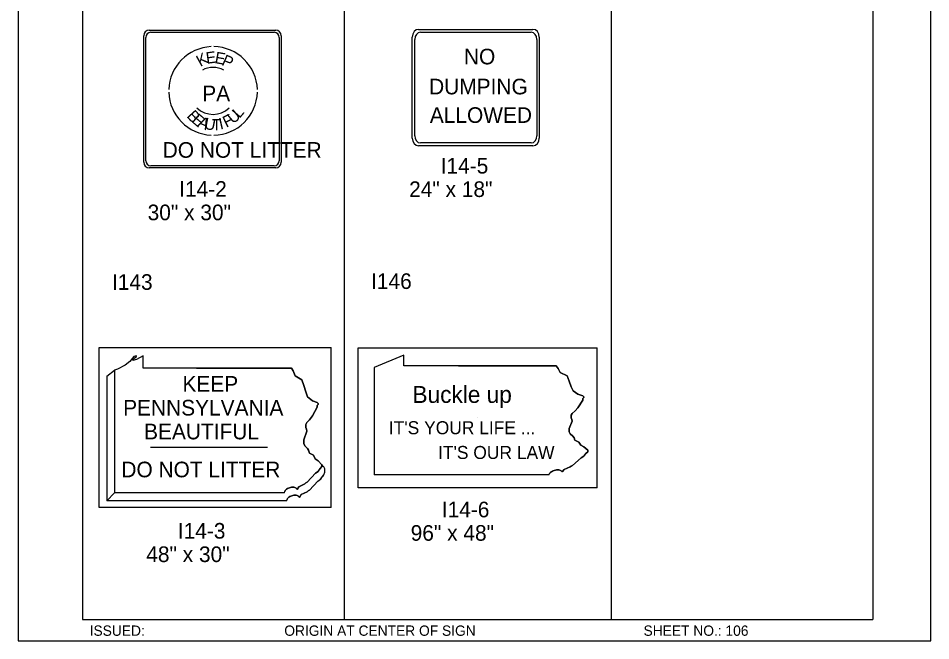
# Model space of a CAD drawing. Extents: x -5299 to 22597, y -19549 to -1808.
# Drawn here: x 14332 to 15033, y -5462 to -4984 of the extents above; entities that cross this region are included whole.
import ezdxf

# ---------------------------------------------------------------- set-up
doc = ezdxf.new("R2010")
doc.units = 0
for name, color, linetype in [('Level 1', 7, 'Continuous'), ('Level 2', 7, 'Continuous'), ('Level 3', 7, 'Continuous'), ('Level 61', 7, 'Continuous')]:
    doc.layers.add(name, color=color, linetype=linetype)

msp = doc.modelspace()

# ---------------------------------------------------------------- linework, layer by layer
at = {"layer": 'Level 1'}
for p, q in [((14381.92, -4645.77), (14381.92, -5445.77)), ((14582.85, -4645.77), (14582.85, -5445.77)), ((14788.01, -4645.77), (14788.01, -5445.77)), ((14988.94, -4645.77), (14988.94, -5445.77)), ((14428.81, -5094.6), (14428.81, -4997.4)), ((14433.04, -4993.17), (14530.24, -4993.17)), ((14434.29, -4994.74), (14528.99, -4994.74)), ((14534.47, -4997.4), (14534.47, -5094.6)), ((14635.19, -5075.98), (14635.19, -4998.46)), ((14640.07, -4992.5), (14727.85, -4992.5)), ((14641.55, -4994.74), (14726.41, -4994.74)), ((14732.73, -4998.46), (14732.73, -5075.98)), ((14430.38, -5093.35), (14430.38, -4998.65)), ((14532.9, -4998.65), (14532.9, -5093.35)), ((14637.04, -5074.2), (14637.04, -5000.25)), ((14730.92, -5000.25), (14730.92, -5074.2)), ((14481.64, -5046), (14481.64, -5046)), ((14727.85, -5081.95), (14640.07, -5081.95)), ((14726.41, -5079.71), (14641.55, -5079.71)), ((14530.24, -5098.83), (14433.04, -5098.83)), ((14528.99, -5097.26), (14434.29, -5097.26)), ((14394.57, -5359.75), (14394.57, -5236.72)), ((14394.57, -5236.72), (14572.74, -5236.72)), ((14572.74, -5359.75), (14572.74, -5236.72)), ((14593.68, -5344.56), (14593.68, -5237)), ((14593.68, -5237), (14777.18, -5237)), ((14628.67, -5242.65), (14605.98, -5252.28)), ((14628.67, -5251.03), (14628.67, -5242.65)), ((14777.18, -5344.56), (14777.18, -5237)), ((14400.53, -5258.98), (14406.51, -5254.2)), ((14685.43, -5290.78), (14685.43, -5290.78)), ((14483.65, -5298.24), (14483.65, -5298.24)), ((14434.08, -5313.47), (14523.85, -5313.47)), ((14758.34, -5327.45), (14764.85, -5321.49)), ((14554.44, -5340.19), (14560.76, -5333.36)), ((14740.45, -5334.75), (14605.95, -5334.75)), ((14740.45, -5334.75), (14605.95, -5334.75)), ((14740.45, -5334.75), (14740.57, -5333.71)), ((14740.45, -5334.75), (14740.57, -5333.71)), ((14740.45, -5334.75), (14740.57, -5333.71)), ((14556.21, -5346.28), (14562.52, -5339.46)), ((14406.48, -5348.58), (14400.51, -5354.55)), ((14537.07, -5348.53), (14406.48, -5348.53)), ((14537.07, -5348.53), (14406.48, -5348.53)), ((14537.07, -5348.53), (14537.19, -5347.34)), ((14537.07, -5348.53), (14537.19, -5347.34)), ((14537.07, -5348.53), (14537.19, -5347.34)), ((14777.18, -5344.56), (14593.68, -5344.56)), ((14538.84, -5354.63), (14400.51, -5354.63)), ((14538.84, -5354.63), (14408.25, -5354.63)), ((14538.84, -5354.63), (14408.25, -5354.63)), ((14538.84, -5354.63), (14538.95, -5353.44)), ((14538.84, -5354.63), (14538.95, -5353.44)), ((14538.84, -5354.63), (14538.95, -5353.44)), ((14572.74, -5359.75), (14394.57, -5359.75)), ((14381.92, -5445.77), (14988.94, -5445.77))]:
    msp.add_line(p, q, dxfattribs=at)
for points in [[(14469.38, -5252.76), (14428.54, -5252.76), (14428.48, -5243.18), (14423.39, -5246.09), (14420.51, -5246.82), (14421.2, -5245.38), (14423.39, -5243.86), (14423.41, -5243.18), (14421.18, -5243.86), (14418.26, -5247.53), (14414.66, -5250.49), (14408.71, -5253.47), (14406.51, -5254.2)], [(14406.51, -5254.2), (14406.48, -5348.53)], [(14560.76, -5333.36), (14562.82, -5331.95), (14564.33, -5329.73), (14565.75, -5328.27), (14565.77, -5326.87), (14562.77, -5323.89), (14560.59, -5322.44), (14559.16, -5319.56), (14556.2, -5318.03), (14555.48, -5315.79), (14554.73, -5314.35), (14552.59, -5312.24), (14551.75, -5310.69), (14551.81, -5307.79), (14554.03, -5301.13), (14553.97, -5299.68), (14553.26, -5298.23), (14553.28, -5296.05), (14553.26, -5296.08), (14554.03, -5294.53), (14556.27, -5292.29), (14558.42, -5289.39), (14562.09, -5282.78), (14562.07, -5282.75), (14562.09, -5281.33), (14562.82, -5280.58), (14562.81, -5279.9), (14562.06, -5279.12), (14558.42, -5277.67), (14554.75, -5274.72), (14553.28, -5271.01), (14551.88, -5266.08), (14550.33, -5261.55), (14545.2, -5258.57), (14543.68, -5254.86), (14542.27, -5252.75), (14469.38, -5252.76)], [(14560.76, -5333.36), (14562.82, -5331.95), (14564.33, -5329.73), (14565.75, -5328.27), (14565.77, -5326.87), (14562.77, -5323.89), (14560.59, -5322.44), (14559.16, -5319.56), (14556.2, -5318.03), (14555.48, -5315.79), (14554.73, -5314.35), (14552.59, -5312.24), (14551.75, -5310.69), (14551.81, -5307.79), (14554.03, -5301.13), (14553.97, -5299.68), (14553.26, -5298.23), (14553.28, -5296.05), (14553.26, -5296.08), (14554.03, -5294.53), (14556.27, -5292.29), (14558.42, -5289.39), (14562.09, -5282.78), (14562.07, -5282.75), (14562.09, -5281.33), (14562.82, -5280.58), (14562.81, -5279.9), (14562.06, -5279.12), (14558.42, -5277.67), (14554.75, -5274.72), (14553.28, -5271.01), (14551.88, -5266.08), (14550.33, -5261.55), (14545.2, -5258.57), (14543.68, -5254.86), (14542.27, -5252.75), (14469.38, -5252.76)], [(14469.38, -5252.76), (14542.27, -5252.75), (14543.68, -5254.86), (14545.2, -5258.57), (14550.33, -5261.55), (14551.88, -5266.08), (14553.28, -5271.01), (14554.75, -5274.72), (14558.42, -5277.67), (14562.06, -5279.12), (14562.81, -5279.9), (14562.82, -5280.58), (14562.09, -5281.33), (14562.07, -5282.75), (14562.09, -5282.78), (14558.42, -5289.39), (14556.27, -5292.29), (14554.03, -5294.53), (14553.26, -5296.08), (14553.28, -5296.05), (14553.26, -5298.23), (14553.97, -5299.68), (14554.03, -5301.13), (14551.81, -5307.79), (14551.75, -5310.69), (14552.59, -5312.24), (14554.73, -5314.35), (14555.48, -5315.79), (14556.2, -5318.03), (14559.16, -5319.56), (14560.59, -5322.44), (14562.77, -5323.89), (14565.77, -5326.87), (14565.75, -5328.27), (14564.33, -5329.73), (14562.92, -5331.81)], [(14605.98, -5252.28), (14605.95, -5334.75)], [(14764.85, -5321.49), (14766.97, -5320.26), (14768.53, -5318.31), (14769.99, -5317.04), (14770, -5315.81), (14766.92, -5313.21), (14764.67, -5311.94), (14763.2, -5309.42), (14760.15, -5308.08), (14759.41, -5306.12), (14758.64, -5304.87), (14756.43, -5303.02), (14755.57, -5301.66), (14755.63, -5299.13), (14757.91, -5293.31), (14757.85, -5292.04), (14757.13, -5290.77), (14757.14, -5288.86), (14757.13, -5288.89), (14757.91, -5287.54), (14760.22, -5285.58), (14762.44, -5283.05), (14766.22, -5277.27), (14766.2, -5277.24), (14766.22, -5276), (14766.97, -5275.34), (14766.95, -5274.74), (14766.18, -5274.06), (14762.44, -5272.8), (14758.65, -5270.22), (14757.14, -5266.98), (14755.7, -5262.67), (14754.11, -5258.7), (14748.82, -5256.1), (14747.25, -5252.86), (14745.81, -5251.02), (14628.67, -5251.03)], [(14764.85, -5321.49), (14766.97, -5320.26), (14768.53, -5318.31), (14769.99, -5317.04), (14770, -5315.81), (14766.92, -5313.21), (14764.67, -5311.94), (14763.2, -5309.42), (14760.15, -5308.08), (14759.41, -5306.12), (14758.64, -5304.87), (14756.43, -5303.02), (14755.57, -5301.66), (14755.63, -5299.13), (14757.91, -5293.31), (14757.85, -5292.04), (14757.13, -5290.77), (14757.14, -5288.86), (14757.13, -5288.89), (14757.91, -5287.54), (14760.22, -5285.58), (14762.44, -5283.05), (14766.22, -5277.27), (14766.2, -5277.24), (14766.22, -5276), (14766.97, -5275.34), (14766.95, -5274.74), (14766.18, -5274.06), (14762.44, -5272.8), (14758.65, -5270.22), (14757.14, -5266.98), (14755.7, -5262.67), (14754.11, -5258.7), (14748.82, -5256.1), (14747.25, -5252.86), (14745.81, -5251.02), (14670.74, -5251.02)], [(14670.74, -5251.02), (14745.81, -5251.02), (14747.25, -5252.86), (14748.82, -5256.1), (14754.11, -5258.7), (14755.7, -5262.67), (14757.14, -5266.98), (14758.65, -5270.22), (14762.44, -5272.8), (14766.18, -5274.06), (14766.95, -5274.74), (14766.97, -5275.34), (14766.22, -5276), (14766.2, -5277.24), (14766.22, -5277.27), (14762.44, -5283.05), (14760.22, -5285.58), (14757.91, -5287.54), (14757.13, -5288.89), (14757.14, -5288.86), (14757.13, -5290.77), (14757.85, -5292.04), (14757.91, -5293.31), (14755.63, -5299.13), (14755.57, -5301.66), (14756.43, -5303.02), (14758.64, -5304.87), (14759.41, -5306.12), (14760.15, -5308.08), (14763.2, -5309.42), (14764.67, -5311.94), (14766.92, -5313.21), (14770, -5315.81), (14769.99, -5317.04), (14768.53, -5318.31), (14767.07, -5320.13)], [(14400.53, -5258.98), (14400.51, -5354.55)], [(14767.07, -5320.13), (14766.97, -5320.26), (14764.85, -5321.49)], [(14740.55, -5333.79), (14740.57, -5333.71), (14740.98, -5333.16), (14741.41, -5332.69), (14742.02, -5332.24), (14742.8, -5331.8), (14743.48, -5331.49), (14744.27, -5331.26), (14745.15, -5331.04), (14746.03, -5330.91), (14746.92, -5330.89), (14747.74, -5330.91), (14748.48, -5331.07), (14749.09, -5331.32), (14749.55, -5331.56), (14750.02, -5331.96), (14750.35, -5332.45), (14751.85, -5330.57), (14756.43, -5328.61), (14757.19, -5327.95), (14758.34, -5327.45)], [(14758.34, -5327.45), (14757.19, -5327.95), (14756.43, -5328.61), (14751.85, -5330.57), (14750.35, -5332.45), (14750.02, -5331.96), (14749.55, -5331.56), (14749.09, -5331.32), (14748.48, -5331.07), (14747.74, -5330.91), (14746.92, -5330.89), (14746.03, -5330.91), (14745.15, -5331.04), (14744.27, -5331.26), (14743.48, -5331.49), (14742.8, -5331.8), (14742.02, -5332.24), (14741.41, -5332.69), (14740.98, -5333.16), (14740.57, -5333.71), (14740.55, -5333.79)], [(14740.55, -5333.79), (14740.57, -5333.71), (14740.98, -5333.16), (14741.41, -5332.69), (14742.02, -5332.24), (14742.8, -5331.8), (14743.48, -5331.49), (14744.27, -5331.26), (14745.15, -5331.04), (14746.03, -5330.91), (14746.92, -5330.89), (14747.74, -5330.91), (14748.48, -5331.07), (14749.09, -5331.32), (14749.55, -5331.56), (14750.02, -5331.96), (14750.35, -5332.45), (14751.85, -5330.57), (14756.43, -5328.61), (14757.19, -5327.95), (14758.34, -5327.45)], [(14562.92, -5331.81), (14562.82, -5331.95), (14560.76, -5333.36)], [(14562.52, -5339.46), (14564.59, -5338.05), (14566.1, -5335.82), (14567.33, -5334.56)], [(14567.33, -5334.56), (14566.78, -5335.13)], [(14537.17, -5347.43), (14537.19, -5347.34), (14537.58, -5346.72), (14538, -5346.18), (14538.59, -5345.66), (14539.36, -5345.16), (14540.01, -5344.81), (14540.78, -5344.53), (14541.63, -5344.29), (14542.49, -5344.14), (14543.36, -5344.12), (14544.15, -5344.14), (14544.87, -5344.32), (14545.46, -5344.61), (14545.91, -5344.89), (14546.36, -5345.34), (14546.68, -5345.91), (14548.13, -5343.76), (14552.59, -5341.51), (14553.33, -5340.76), (14554.44, -5340.19)], [(14554.44, -5340.19), (14553.33, -5340.76), (14552.59, -5341.51), (14548.13, -5343.76), (14546.68, -5345.91), (14546.36, -5345.34), (14545.91, -5344.89), (14545.46, -5344.61), (14544.87, -5344.32), (14544.15, -5344.14), (14543.36, -5344.12), (14542.49, -5344.14), (14541.63, -5344.29), (14540.78, -5344.53), (14540.01, -5344.81), (14539.36, -5345.16), (14538.59, -5345.66), (14538, -5346.18), (14537.58, -5346.72), (14537.19, -5347.34), (14537.17, -5347.43)], [(14537.17, -5347.43), (14537.19, -5347.34), (14537.58, -5346.72), (14538, -5346.18), (14538.59, -5345.66), (14539.36, -5345.16), (14540.01, -5344.81), (14540.78, -5344.53), (14541.63, -5344.29), (14542.49, -5344.14), (14543.36, -5344.12), (14544.15, -5344.14), (14544.87, -5344.32), (14545.46, -5344.61), (14545.91, -5344.89), (14546.36, -5345.34), (14546.68, -5345.91), (14548.13, -5343.76), (14552.59, -5341.51), (14553.33, -5340.76), (14554.44, -5340.19)], [(14566.06, -5335.87), (14564.68, -5337.91)], [(14566.78, -5335.13), (14566.1, -5335.82), (14566.06, -5335.87)], [(14538.93, -5353.53), (14538.95, -5353.44), (14539.35, -5352.81), (14539.76, -5352.28), (14540.36, -5351.76), (14541.12, -5351.26), (14541.78, -5350.9), (14542.54, -5350.63), (14543.4, -5350.39), (14544.25, -5350.23), (14545.12, -5350.22), (14545.92, -5350.23), (14546.63, -5350.42), (14547.23, -5350.7), (14547.67, -5350.98), (14548.13, -5351.44), (14548.45, -5352), (14549.9, -5349.85), (14554.36, -5347.61), (14555.09, -5346.86), (14556.21, -5346.28)], [(14556.21, -5346.28), (14555.09, -5346.86), (14554.36, -5347.61), (14549.9, -5349.85), (14548.45, -5352), (14548.13, -5351.44), (14547.67, -5350.98), (14547.23, -5350.7), (14546.63, -5350.42), (14545.92, -5350.23), (14545.12, -5350.22), (14544.25, -5350.23), (14543.4, -5350.39), (14542.54, -5350.63), (14541.78, -5350.9), (14541.12, -5351.26), (14540.36, -5351.76), (14539.76, -5352.28), (14539.35, -5352.81), (14538.95, -5353.44), (14538.93, -5353.53)], [(14538.93, -5353.53), (14538.95, -5353.44), (14539.35, -5352.81), (14539.76, -5352.28), (14540.36, -5351.76), (14541.12, -5351.26), (14541.78, -5350.9), (14542.54, -5350.63), (14543.4, -5350.39), (14544.25, -5350.23), (14545.12, -5350.22), (14545.92, -5350.23), (14546.63, -5350.42), (14547.23, -5350.7), (14547.67, -5350.98), (14548.13, -5351.44), (14548.45, -5352), (14549.9, -5349.85), (14554.36, -5347.61), (14555.09, -5346.86), (14556.21, -5346.28)]]:
    msp.add_lwpolyline(points, dxfattribs=at)
for centre, radius, start, end in [((14433.04, -4997.39), 4.23, 90, 180), ((14434.29, -4998.65), 3.91, 90, 180), ((14528.99, -4998.65), 3.91, 0, 90), ((14530.24, -4997.39), 4.23, 0, 90), ((14482.13, -5039.77), 34.02, 92.51504, 178.31574), ((14482.13, -5039.77), 34.02, 1.68426, 89.14617), ((14482.13, -5039.77), 18.02, 62.96212, 117.03788), ((14482.13, -5039.77), 34.02, 181.68426, 267.48496), ((14482.13, -5039.77), 34.02, 270.85383, 358.31574), ((14482.13, -5039.77), 18.02, 226.36886, 313.63114), ((14433.04, -5094.6), 4.23, 180, 270), ((14434.29, -5093.35), 3.91, 180, 270), ((14528.99, -5093.35), 3.91, 270, 0), ((14530.24, -5094.6), 4.23, 270, 0)]:
    msp.add_arc(centre, radius, start, end, dxfattribs=at)
for centre, major_axis, start_param, end_param in [((14640.07, -4998.46), (0, -5.96), 3.141593, 4.712389), ((14641.55, -5000.25), (0, -5.52), 3.141593, 4.712389), ((14726.41, -5000.25), (0, 5.52), 4.712389, 6.283185), ((14727.85, -4998.46), (0, 5.96), 4.712389, 6.283185), ((14641.55, -5074.2), (0, -5.52), 4.712389, 6.283185), ((14726.41, -5074.2), (0, 5.52), 3.141593, 4.712389), ((14640.07, -5075.99), (0, -5.96), 4.712389, 6.283185), ((14727.85, -5075.99), (0, -5.96), 0, 1.570796)]:
    msp.add_ellipse(centre, major_axis=major_axis, ratio=0.817773, start_param=start_param, end_param=end_param, dxfattribs=at)
msp.add_spline([(14567.33, -5334.56), (14567.73, -5333.23), (14568.01, -5331.72), (14568.01, -5330.62), (14567.7, -5329.58), (14567.15, -5328.6), (14565.77, -5326.87)], degree=3, dxfattribs=at)
at = {"layer": 'Level 3'}
msp.add_line((14683.98, -5037.23), (14683.98, -5037.23), dxfattribs=at)
at = {"layer": 'Level 61'}
msp.add_lwpolyline([(14332.44, -5462.05), (15033.49, -5462.05), (15033.49, -4609.67), (14332.44, -4609.67)], close=True, dxfattribs=at)

# ---------------------------------------------------------------- texts
at = {"layer": 'Level 1'}
for s, height, p in [('NO', 12, (14674.87, -5019.39)), ('DUMPING', 12, (14648.09, -5042.43)), ('PA', 12, (14473.81, -5047.74)), ('ALLOWED', 12, (14648.66, -5064.34)), ('T', 8.75, (14481.34, -5070.05)), ('DO NOT LITTER', 12, (14443.43, -5091.11)), ('KEEP', 12, (14458.6, -5270.78)), ('Buckle up', 13, (14635.32, -5279.39)), ('PENNSYLVANIA', 12, (14413.05, -5289.07)), ('BEAUTIFUL', 12, (14429.12, -5307.36)), ("IT'S YOUR LIFE ...", 10, (14617.18, -5303.44)), ("IT'S OUR LAW", 10, (14654.98, -5322.46)), ('DO NOT LITTER', 12, (14411.68, -5336.52))]:
    msp.add_text(s, height=height, dxfattribs=at).set_placement(p)
at = {"layer": 'Level 2'}
for s, height, rotation, p in [('K', 8.9, 29.00546, (14472.33, -5021.51)), ('E', 8.9, 8.01533, (14477.23, -5019.06)), ('E', 8.9, 349.97879, (14483, -5018.36)), ('P', 8.9, 336.01508, (14488.08, -5019.59)), ('B', 8.75, 312.00673, (14461.39, -5059.38)), ('U', 8.75, 39.00849, (14497.44, -5065.5)), ('L', 8.75, 48.99292, (14502.34, -5061.3)), ('E', 8.75, 319.99292, (14465.07, -5063.23)), ('A', 8.75, 334.99672, (14469.62, -5066.73)), ('U', 8.75, 349.02513, (14474.87, -5068.83)), ('I', 8.75, 12.99462, (14487.64, -5069.53)), ('F', 8.75, 25.97439, (14492.19, -5068.13))]:
    msp.add_text(s, height=height, rotation=rotation, dxfattribs=at).set_placement(p)
for s, p in [('I143', (14404.45, -5192.55)), ('I146', (14603.52, -5191.88))]:
    msp.add_text(s, height=12, dxfattribs=at).set_placement(p)
at = {"layer": 'Level 3'}
for s, height, p in [('I14-5', 12, (14656.98, -5103.25)), ('I14-2', 12, (14456.08, -5121.09)), ('24" x 18"', 12, (14632.75, -5121.25)), ('30" x 30"', 12, (14431.84, -5139.09)), ('I14-6', 12, (14657.84, -5367.25)), ('I14-3', 12, (14455.04, -5383.62)), ('96" x 48"', 12, (14633.93, -5385.25)), ('48" x 30"', 12, (14430.8, -5401.62)), ('ISSUED:', 7.918, (14387.29, -5458.26)), ('ORIGIN AT CENTER OF SIGN', 7.9181, (14536.82, -5458.26)), ('SHEET NO.: 106', 7.918, (14812.83, -5458.26))]:
    msp.add_text(s, height=height, dxfattribs=at).set_placement(p)

doc.saveas('drawing.dxf')
